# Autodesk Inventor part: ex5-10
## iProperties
Created: 2006-03
Part Number: ex5-10
Document SubType Name: Modeling
Designer: Elise Moss
Author: Elise Moss
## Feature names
1. Loft1
2. Shell1
3. Extrusion1
4. Sweep1
